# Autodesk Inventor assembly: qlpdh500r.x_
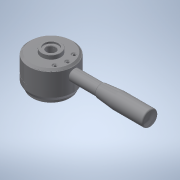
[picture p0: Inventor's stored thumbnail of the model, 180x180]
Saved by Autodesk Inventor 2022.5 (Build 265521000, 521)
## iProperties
Part Number: qlpdh500r.x_
Material: 一般
Document SubType Name: Assembly
Designer: ImaoCorp
Sending System: SOLIDWORKS 2017-2017317
MC: AMD64
MC_MODEL: Intel64 Family 6 Model 60 Stepping 3, GenuineIntel
OS: Windows_NT
FRU: Parasolid Version 29.0, build 201,  4-17-2017
FORMAT: text
GUISE: transmit
KEY: qlpdh500r
FILE: qlpdh500r.x_t
DATE: Wed Sep 04 15:44:28 2019
Author: ImaoCorp
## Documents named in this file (5)
- X:\14_SW2022-Inv2022\00_全2023-1023新製品(TCC)まで\q\qlpdh500r\QLPDH500R.iam
- X:\14_SW2022-Inv2022\00_全2023-1023新製品(TCC)まで\q\qlpdh500r\qlpdh500r_01.ipt
- X:\14_SW2022-Inv2022\00_全2023-1023新製品(TCC)まで\q\qlpdh500r\qlpdh500r_02.ipt
- X:\14_SW2022-Inv2022\00_全2023-1023新製品(TCC)まで\q\qlpdh500r\qlpdh500r_03.ipt
- X:\14_SW2022-Inv2022\00_全2023-1023新製品(TCC)まで\q\qlpdh500r\qlpdh500r_04.ipt
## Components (4 placed, 4 different names)
1. qlpdh500r_01
2. qlpdh500r_02
3. qlpdh500r_03
4. qlpdh500r_04
